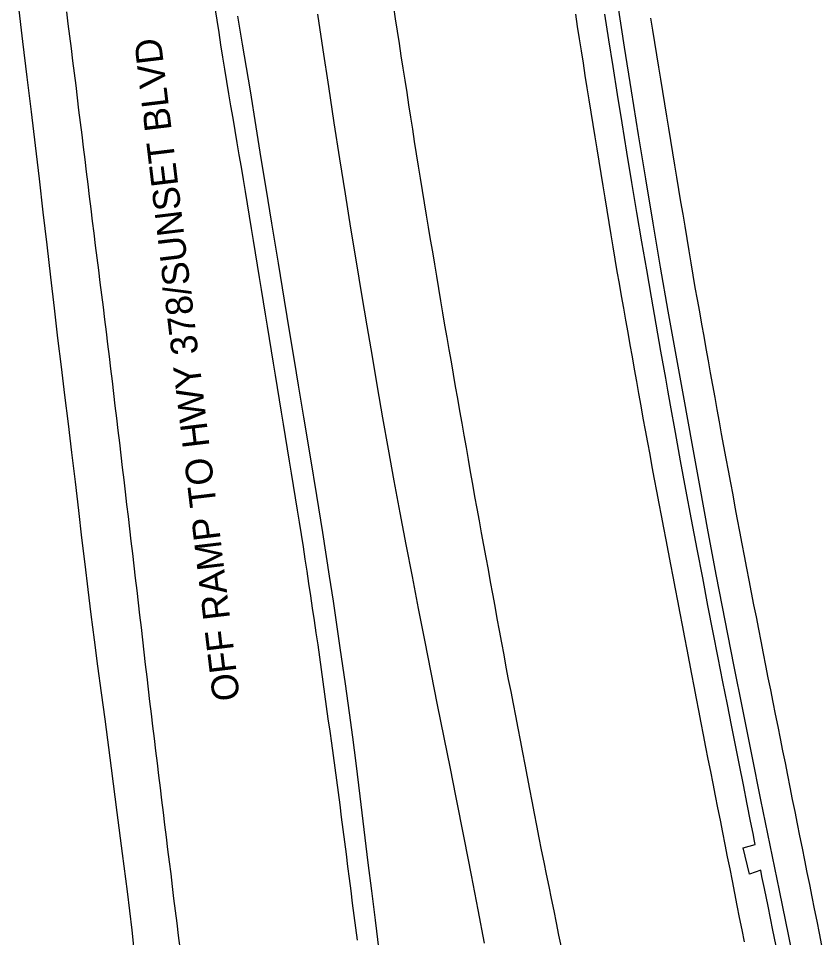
# Model space of a CAD drawing. Extents: x 1948091 to 1975253, y 787267 to 823306.
# Drawn here: x 1966319.5 to 1966481.3, y 790203 to 790388.1 of the extents above; entities that cross this region are included whole.
import ezdxf

# ---------------------------------------------------------------- set-up
doc = ezdxf.new("R2010")
doc.units = 0
for name, color, linetype in [('RD_EX_Pavement_Markings', 7, 'Continuous'), ('RD_EX_Road', 7, 'Continuous'), ('RD_TX_RoadID', 7, 'Continuous')]:
    doc.layers.add(name, color=color, linetype=linetype)

msp = doc.modelspace()

# ---------------------------------------------------------------- linework, layer by layer
at = {"layer": 'RD_EX_Pavement_Markings'}
for points in [[(1966387.79, 790202.46), (1966387.47, 790204.94), (1966387.15, 790207.42), (1966386.84, 790209.9), (1966386.52, 790212.38), (1966386.2, 790214.86), (1966385.89, 790217.34), (1966385.57, 790219.82), (1966385.25, 790222.3), (1966384.93, 790224.78), (1966384.62, 790227.26), (1966384.3, 790229.74), (1966383.98, 790232.22), (1966383.65, 790234.7), (1966383.31, 790237.17), (1966382.96, 790239.65), (1966382.62, 790242.12), (1966382.28, 790244.6), (1966381.93, 790247.08), (1966381.59, 790249.55), (1966381.24, 790252.03), (1966380.9, 790254.5), (1966380.56, 790256.98), (1966380.21, 790259.46), (1966379.87, 790261.93), (1966379.51, 790264.41), (1966379.14, 790266.88), (1966378.77, 790269.35), (1966378.39, 790271.82), (1966378.02, 790274.29), (1966377.65, 790276.77), (1966377.28, 790279.24), (1966376.91, 790281.71), (1966376.53, 790284.18), (1966376.13, 790286.65), (1966375.73, 790289.12), (1966375.33, 790291.58), (1966374.93, 790294.05), (1966374.53, 790296.52), (1966374.13, 790298.99), (1966373.73, 790301.45), (1966373.33, 790303.92), (1966372.93, 790306.39), (1966372.53, 790308.86), (1966372.13, 790311.32), (1966371.73, 790313.79), (1966371.32, 790316.26), (1966370.91, 790318.72), (1966370.5, 790321.19), (1966370.09, 790323.65), (1966369.68, 790326.12), (1966369.27, 790328.58), (1966368.86, 790331.05), (1966368.45, 790333.52), (1966368.05, 790335.98), (1966367.64, 790338.45), (1966367.24, 790340.91), (1966366.84, 790343.38), (1966366.44, 790345.85), (1966366.03, 790348.31), (1966365.63, 790350.78), (1966365.23, 790353.25), (1966364.83, 790355.71), (1966364.42, 790358.18), (1966364, 790360.65), (1966363.58, 790363.11), (1966363.16, 790365.57), (1966362.74, 790368.04), (1966362.32, 790370.5), (1966361.9, 790372.96), (1966361.48, 790375.43), (1966361.08, 790377.89), (1966360.7, 790380.36), (1966360.31, 790382.83), (1966359.92, 790385.3), (1966359.53, 790387.77), (1966359.15, 790390.24)], [(1966395.05, 790390.5), (1966395.43, 790388.03), (1966395.81, 790385.56), (1966396.19, 790383.09), (1966396.58, 790380.62), (1966396.96, 790378.15), (1966397.34, 790375.68), (1966397.73, 790373.21), (1966398.11, 790370.74), (1966398.49, 790368.27), (1966398.88, 790365.8), (1966399.26, 790363.33), (1966399.64, 790360.86), (1966400.02, 790358.39), (1966400.44, 790355.93), (1966400.85, 790353.46), (1966401.26, 790351), (1966401.67, 790348.53), (1966402.08, 790346.06), (1966402.49, 790343.6), (1966402.91, 790341.13), (1966403.32, 790338.67), (1966403.73, 790336.2), (1966404.14, 790333.74), (1966404.55, 790331.27), (1966404.96, 790328.81), (1966405.37, 790326.34), (1966405.8, 790323.88), (1966406.23, 790321.42), (1966406.66, 790318.95), (1966407.09, 790316.49), (1966407.52, 790314.03), (1966407.96, 790311.57), (1966408.39, 790309.11), (1966408.82, 790306.64), (1966409.25, 790304.18), (1966409.68, 790301.72), (1966410.12, 790299.26), (1966410.55, 790296.8), (1966410.98, 790294.34), (1966411.41, 790291.87), (1966411.86, 790289.41), (1966412.31, 790286.96), (1966412.76, 790284.5), (1966413.21, 790282.04), (1966413.66, 790279.58), (1966414.11, 790277.12), (1966414.57, 790274.66), (1966415.02, 790272.21), (1966415.47, 790269.75), (1966415.92, 790267.29), (1966416.37, 790264.83), (1966416.82, 790262.37), (1966417.27, 790259.92), (1966417.73, 790257.46), (1966418.2, 790255), (1966418.68, 790252.55), (1966419.15, 790250.1), (1966419.62, 790247.64), (1966420.1, 790245.19), (1966420.57, 790242.73), (1966421.04, 790240.28), (1966421.52, 790237.83), (1966421.99, 790235.37), (1966422.46, 790232.92), (1966422.94, 790230.46), (1966423.41, 790228.01), (1966423.88, 790225.56), (1966424.36, 790223.1), (1966424.84, 790220.65), (1966425.34, 790218.2), (1966425.84, 790215.75), (1966426.34, 790213.3), (1966426.84, 790210.86), (1966427.34, 790208.41), (1966427.84, 790205.96), (1966428.34, 790203.51), (1966428.84, 790201.06)], [(1966329.17, 790389.5), (1966329.49, 790387.02), (1966329.8, 790384.54), (1966330.12, 790382.06), (1966330.43, 790379.58), (1966330.73, 790377.1), (1966331.04, 790374.62), (1966331.34, 790372.14), (1966331.64, 790369.66), (1966331.95, 790367.18), (1966332.25, 790364.7), (1966332.55, 790362.21), (1966332.86, 790359.73), (1966333.16, 790357.25), (1966333.46, 790354.77), (1966333.77, 790352.29), (1966334.07, 790349.81), (1966334.37, 790347.33), (1966334.68, 790344.85), (1966334.99, 790342.37), (1966335.3, 790339.89), (1966335.62, 790337.41), (1966335.93, 790334.93), (1966336.24, 790332.45), (1966336.55, 790329.97), (1966336.86, 790327.49), (1966337.17, 790325.01), (1966337.48, 790322.53), (1966337.78, 790320.05), (1966338.07, 790317.57), (1966338.36, 790315.09), (1966338.66, 790312.6), (1966338.95, 790310.12), (1966339.25, 790307.64), (1966339.54, 790305.16), (1966339.84, 790302.67), (1966340.13, 790300.19), (1966340.43, 790297.71), (1966340.72, 790295.23), (1966341.01, 790292.75), (1966341.31, 790290.26), (1966341.6, 790287.78), (1966341.9, 790285.3), (1966342.18, 790282.82), (1966342.47, 790280.33), (1966342.76, 790277.85), (1966343.05, 790275.37), (1966343.34, 790272.88), (1966343.63, 790270.4), (1966343.92, 790267.92), (1966344.21, 790265.43), (1966344.5, 790262.95), (1966344.79, 790260.47), (1966345.07, 790257.99), (1966345.36, 790255.5), (1966345.65, 790253.02), (1966345.94, 790250.54), (1966346.23, 790248.05), (1966346.53, 790245.57), (1966346.83, 790243.09), (1966347.14, 790240.61), (1966347.44, 790238.13), (1966347.75, 790235.65), (1966348.05, 790233.16), (1966348.35, 790230.68), (1966348.66, 790228.2), (1966348.96, 790225.72), (1966349.27, 790223.24), (1966349.57, 790220.76), (1966349.88, 790218.28), (1966350.18, 790215.8), (1966350.48, 790213.31), (1966350.78, 790210.83), (1966351.09, 790208.35), (1966351.39, 790205.87), (1966351.69, 790203.39), (1966351.99, 790200.91)], [(1966431.72, 790389), (1966432.1, 790386.53), (1966432.49, 790384.06), (1966432.88, 790381.59), (1966433.26, 790379.13), (1966433.65, 790376.66), (1966434.04, 790374.19), (1966434.42, 790371.72), (1966434.82, 790369.25), (1966435.22, 790366.78), (1966435.63, 790364.31), (1966436.03, 790361.85), (1966436.44, 790359.38), (1966436.84, 790356.91), (1966437.25, 790354.45), (1966437.65, 790351.98), (1966438.06, 790349.51), (1966438.46, 790347.05), (1966438.87, 790344.58), (1966439.27, 790342.11), (1966439.68, 790339.65), (1966440.08, 790337.18), (1966440.52, 790334.72), (1966440.96, 790332.26), (1966441.39, 790329.8), (1966441.83, 790327.34), (1966442.27, 790324.88), (1966442.71, 790322.42), (1966443.14, 790319.95), (1966443.58, 790317.49), (1966444.02, 790315.03), (1966444.46, 790312.57), (1966444.89, 790310.11), (1966445.33, 790307.65), (1966445.77, 790305.19), (1966446.22, 790302.73), (1966446.69, 790300.27), (1966447.15, 790297.82), (1966447.61, 790295.36), (1966448.08, 790292.91), (1966448.54, 790290.45), (1966449, 790287.99), (1966449.47, 790285.54), (1966449.93, 790283.08), (1966450.4, 790280.63), (1966450.86, 790278.17), (1966451.32, 790275.71), (1966451.79, 790273.26), (1966452.26, 790270.8), (1966452.73, 790268.35), (1966453.21, 790265.9), (1966453.68, 790263.44), (1966454.16, 790260.99), (1966454.63, 790258.53), (1966455.11, 790256.08), (1966455.58, 790253.63), (1966456.06, 790251.17), (1966456.53, 790248.72), (1966457.01, 790246.26), (1966457.48, 790243.81), (1966457.95, 790241.36), (1966458.43, 790238.9), (1966458.92, 790236.45), (1966459.4, 790234), (1966459.89, 790231.55), (1966460.37, 790229.1), (1966460.86, 790226.65), (1966461.34, 790224.19), (1966461.83, 790221.74), (1966462.31, 790219.29), (1966462.8, 790216.84), (1966463.28, 790214.39), (1966463.77, 790211.93), (1966464.25, 790209.48), (1966464.74, 790207.03), (1966465.24, 790204.58), (1966465.73, 790202.13)], [(1966446.87, 790388.21), (1966447.27, 790385.75), (1966447.67, 790383.28), (1966448.07, 790380.81), (1966448.47, 790378.34), (1966448.86, 790375.88), (1966449.26, 790373.41), (1966449.66, 790370.94), (1966450.06, 790368.47), (1966450.46, 790366.01), (1966450.86, 790363.54), (1966451.26, 790361.07), (1966451.67, 790358.61), (1966452.09, 790356.14), (1966452.5, 790353.67), (1966452.91, 790351.21), (1966453.33, 790348.74), (1966453.74, 790346.28), (1966454.16, 790343.81), (1966454.57, 790341.35), (1966454.98, 790338.88), (1966455.4, 790336.42), (1966455.81, 790333.95), (1966456.25, 790331.49), (1966456.69, 790329.03), (1966457.13, 790326.57), (1966457.57, 790324.11), (1966458.01, 790321.65), (1966458.45, 790319.19), (1966458.9, 790316.73), (1966459.34, 790314.27), (1966459.78, 790311.81), (1966460.22, 790309.35), (1966460.66, 790306.89), (1966461.1, 790304.43), (1966461.56, 790301.97), (1966462.02, 790299.52), (1966462.48, 790297.06), (1966462.95, 790294.6), (1966463.41, 790292.15), (1966463.87, 790289.69), (1966464.33, 790287.23), (1966464.79, 790284.78), (1966465.25, 790282.32), (1966465.72, 790279.86), (1966466.19, 790277.41), (1966466.67, 790274.96), (1966467.15, 790272.5), (1966467.63, 790270.05), (1966468.11, 790267.6), (1966468.59, 790265.14), (1966469.08, 790262.69), (1966469.56, 790260.24), (1966470.04, 790257.79), (1966470.52, 790255.33), (1966471, 790252.88), (1966471.49, 790250.43), (1966471.99, 790247.98), (1966472.48, 790245.53), (1966472.97, 790243.08), (1966473.46, 790240.63), (1966473.95, 790238.18), (1966474.44, 790235.73), (1966474.93, 790233.28), (1966475.42, 790230.83), (1966475.91, 790228.38), (1966476.41, 790225.92), (1966476.9, 790223.47), (1966477.39, 790221.02), (1966477.88, 790218.57), (1966478.37, 790216.12), (1966478.86, 790213.67), (1966479.35, 790211.22), (1966479.84, 790208.77), (1966480.34, 790206.32), (1966480.83, 790203.87), (1966481.32, 790201.42)]]:
    msp.add_lwpolyline(points, dxfattribs=at)
at = {"layer": 'RD_EX_Road'}
for points in [[(1966343.23, 790196.5), (1966342.39, 790204.46), (1966341.48, 790212.25), (1966340.5, 790219.94), (1966339.43, 790228.17), (1966338.27, 790237.1), (1966336.96, 790246.98), (1966336.24, 790252.3), (1966335.52, 790257.68), (1966334.83, 790262.95), (1966334.18, 790268.09), (1966333.56, 790273.12), (1966332.95, 790278.2), (1966332.31, 790283.51), (1966331.65, 790289.05), (1966330.97, 790294.82), (1966330.28, 790300.68), (1966329.58, 790306.49), (1966328.88, 790312.24), (1966328.17, 790317.95), (1966327.46, 790323.74), (1966326.74, 790329.77), (1966326.01, 790336.02), (1966325.27, 790342.5), (1966324.52, 790349.13), (1966323.75, 790355.81), (1966322.95, 790362.55), (1966322.12, 790369.35), (1966321.28, 790376.3), (1966320.4, 790383.49), (1966319.49, 790390.93)], [(1966476.59, 790194.11), (1966474.71, 790203.28), (1966472.84, 790212.45), (1966470.96, 790221.62), (1966469.1, 790230.77), (1966467.26, 790239.87), (1966465.44, 790248.92), (1966463.65, 790257.92), (1966461.89, 790266.88), (1966460.17, 790275.82), (1966458.48, 790284.75), (1966456.83, 790293.65), (1966455.21, 790302.54), (1966453.6, 790311.42), (1966452.01, 790320.3), (1966450.44, 790329.18), (1966448.89, 790338.05), (1966447.37, 790346.93), (1966445.88, 790355.81), (1966444.42, 790364.7), (1966443, 790373.56), (1966441.6, 790382.37), (1966440.24, 790391.12)], [(1966363.64, 790388.61), (1966364.59, 790382.97), (1966366.16, 790373.53), (1966367.33, 790366.31), (1966368.37, 790359.92), (1966369.36, 790353.92), (1966370.52, 790346.87), (1966371.83, 790338.82), (1966373.05, 790331.37), (1966374.13, 790324.83), (1966375.06, 790319.24), (1966375.89, 790314.28), (1966376.97, 790307.83), (1966378.31, 790299.83), (1966379.59, 790292.07), (1966380.78, 790284.59), (1966382.14, 790275.76), (1966382.89, 790270.74), (1966384.28, 790261.34), (1966385.34, 790254.08), (1966386.16, 790248.29), (1966386.8, 790243.33), (1966387.45, 790238.1), (1966388.26, 790231.5), (1966389.3, 790223.08), (1966389.93, 790218.03), (1966390.64, 790212.43), (1966391.38, 790206.48), (1966392.12, 790200.41)], [(1966379.76, 790389.02), (1966380.86, 790381.79), (1966381.97, 790374.44), (1966383.07, 790367.09), (1966384.19, 790359.88), (1966385.31, 790352.82), (1966386.43, 790345.89), (1966387.55, 790339.13), (1966388.64, 790332.56), (1966389.7, 790326.19), (1966390.74, 790320.02), (1966391.79, 790313.9), (1966392.88, 790307.69), (1966394, 790301.39), (1966395.17, 790295), (1966396.36, 790288.56), (1966397.57, 790282.14), (1966398.8, 790275.72), (1966400.05, 790269.31), (1966401.31, 790262.88), (1966402.6, 790256.4), (1966403.9, 790249.87), (1966405.22, 790243.29), (1966406.47, 790237.06), (1966407.57, 790231.56), (1966409.31, 790222.78), (1966410.71, 790215.57), (1966412.05, 790208.55), (1966413.33, 790201.84)], [(1966472.69, 790198.73), (1966471.51, 790204.48), (1966470.53, 790209.29), (1966469.79, 790212.91), (1966469.3, 790215.32), (1966469.05, 790216.55), (1966466.81, 790215.76), (1966465.53, 790221.08), (1966467.96, 790221.72), (1966467.83, 790222.39), (1966467.51, 790223.97), (1966467.02, 790226.47), (1966466.34, 790229.89), (1966465.56, 790233.79), (1966464.78, 790237.74), (1966463.98, 790241.73), (1966463.17, 790245.76), (1966462.33, 790249.97), (1966461.43, 790254.5), (1966460.48, 790259.33), (1966459.48, 790264.47), (1966458.43, 790269.87), (1966457.36, 790275.46), (1966456.26, 790281.24), (1966455.13, 790287.22), (1966454, 790293.22), (1966452.92, 790299.05), (1966451.88, 790304.73), (1966450.88, 790310.24), (1966450.34, 790313.25), (1966449.91, 790315.68), (1966448.94, 790321.11), (1966447.98, 790326.53), (1966447.03, 790331.96), (1966446.08, 790337.47), (1966445.1, 790343.17), (1966444.11, 790349.04), (1966443.1, 790355.1), (1966442.1, 790361.17), (1966441.14, 790367.09), (1966440.21, 790372.84), (1966439.32, 790378.43), (1966438.47, 790383.82), (1966437.66, 790388.98)]]:
    msp.add_lwpolyline(points, dxfattribs=at)

# ---------------------------------------------------------------- texts
at = {"layer": 'RD_TX_RoadID'}
msp.add_text('OFF RAMP TO HWY 378/SUNSET BLVD', height=5.4, rotation=96.825, dxfattribs=at).set_placement((1966364.12, 790250.96))

doc.saveas('drawing.dxf')
